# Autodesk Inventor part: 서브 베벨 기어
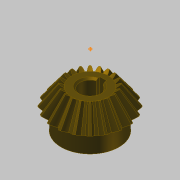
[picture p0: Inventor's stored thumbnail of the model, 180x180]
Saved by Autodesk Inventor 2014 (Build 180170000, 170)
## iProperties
Created: 2016-04
Part Number: 서브 베벨 기어
Material: 강철, 탄소
Document SubType Name: Modeling
Designer: mdu
Categories: <?xml version="1.0" encoding="UTF-16"?> <MemberInstance><Categories><FamilyTemplate><FamilyTemplateParameter ValueType="xs:double" Id="1" ObjectReferenceKey="da
Mass: 135.037 g
Surface Area: 63.6518 cm^2
Volume: 17.1585 cm^3
Density: 7.87 g/cm^3
Appearance: Brindle
CustomPartVersion: 1
Author: mdu
Revision Number: 1
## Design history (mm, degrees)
node "맨 위 점"
node "메쉬 평면2"
sketch "톱니 본체 스케치"
  geometry: L1 (0, 0)-(18.003, -31.331); L2 (18.003, -31.331)-(21.664, -28.891); L3 (21.664, -28.891)-(0, 0); L4 (20, -30)-(0, 0); L5 (10.813, -18.818)-(13.012, -17.352); L6 (18.003, -31.331)-(10.813, -18.818); L7 (21.664, -28.891)-(13.012, -17.352); L8 (0, -39.387)-(0, 6.564) reference; L9 (0, -30)-(21.664, -30)
  constraints: 16 end point, 4 point on line, 3 perpendicular, 2 collinear, 1 horizontal alignment, 1 vertical alignment
  dimensions: "d0" = 40 diameter of L4.start L8 (= da_de); "d1" = 36.00616 diameter of L1.end L8 (= da_dfe); "d2" = 43.3282 diameter of L2.end L8 (= da_dae); "d3" = 14.4 distance between parallel lines of L2 L5 (= da_b); "d4" = 28.8906 vertical distance of L2.end L1.start (= da_ve)
revolve "톱니 본체" sketch "톱니 본체 스케치" stored, may be unused: angle "d5" = 90 deg
node "시작점"
node "톱니 평면"
sketch "시작 스케치"
  geometry: L1 (0, -23.505)-(0, 10.645) reference; L2 (-0.834, -2.928)-(0.834, -2.928); A1 r 8.898 centre (-9.698, -3.713) between (-0.834, -2.928) and (-3.903, 3.04); A2 r 8.898 centre (9.698, -3.713) between (3.903, 3.04) and (0.834, -2.928); A3 r 27.357 centre (0, -24.037) between (3.903, 3.04) and (-3.903, 3.04); 1 further point
  constraints: 6 point on circle, 3 centre point, 3 symmetric about line, 2 end point, 1 coincident, 1 perpendicular, 1 other
  dimensions: "d7" = 8.89846 radius of A1 (= fd_rr); "d8" = 9.69794 horizontal distance of point (0, -24.037) A1.centre (= fd_x); "d9" = 20.32439 vertical distance of point (0, -24.037) A1.centre (= fd_y); "d57" = 27.35701 radius of A3 (= 0.5 x fd_dva + 0.3 x da_he); "d58" = 21.10901 distance from line of A3.centre L2 (= 0.5 x fd_dva - 1.12 x da_he)
node "끝점"
  node "끝 평면"
sketch "3D 스케치 오른쪽"
  node "Helical Curve Right" dims "d65" = 229.90621 (computed from da_dm, da_delta, da_beta), "d66" = 31.5, "d67" = 40 (= da_de), "d68" = -5.88003 (= -da_delta), "d69" = 12.16458 (computed from fd_loft, da_delta)
node "끝 평면 오른쪽"
sketch "끝 스케치 오른쪽"
  geometry: L1 (0, -22.649)-(0, 12.15) reference; L2 (-0.497, -1.72)-(0.497, -1.72); A1 r 5.299 centre (-5.775, -2.187) between (-0.497, -1.72) and (-2.324, 1.834); A2 r 5.299 centre (5.775, -2.187) between (2.324, 1.834) and (0.497, -1.72); A3 r 16.291 centre (0, -14.29) between (2.324, 1.834) and (-2.324, 1.834); 1 further point
  constraints: 6 point on circle, 3 centre point, 3 symmetric about line, 2 end point, 1 coincident, 1 perpendicular, 1 other
  dimensions: "d70" = 5.77526 horizontal distance of A3.centre A1.centre (computed from fd_x, fd_ratio); "d71" = 12.10346 vertical distance of point (0, -14.29) A1.centre (computed from fd_y, fd_ratio); "d72" = 5.29916 radius of A1 (computed from fd_rr, fd_ratio); "d73" = 12.57071 distance from line of point (0, -14.29) L2 (computed from d58, fd_ratio); "d74" = 16.29149 radius of A3 (computed from d57, fd_ratio)
feature "로프트 오른쪽" sketch "끝 스케치 오른쪽" dims "d75" = 0, "d77" = 0, "d79" = 0, "d80" = 90 deg, "d85" = 20, "d92" = 90 deg, "d93" = 90 deg, "da_teethtype" = 0 [user parameter]
sketch "3D 스케치 왼쪽"
  node "Helical Curve Left" dims "d26" = 229.90621 (computed from da_dm, da_delta, da_beta), "d27" = 12.16458 (computed from fd_loft, da_delta), "d28" = 40 (= da_de), "d29" = -5.88003 (= -da_delta)
node "끝 평면 왼쪽"
sketch "끝 스케치 왼쪽" dims "d56" = 10.82768 (derived)
  geometry: L1 (0, -35.087)-(0, 18.089) reference; L2 (-0.497, -1.716)-(0.497, -1.716); A1 r 5.299 centre (-5.775, -2.183) between (-0.497, -1.716) and (-2.324, 1.838); A2 r 5.299 centre (5.775, -2.183) between (2.324, 1.838) and (0.497, -1.716); A3 r 16.291 centre (0, -14.287) between (2.324, 1.838) and (-2.324, 1.838); 2 further points; 1 other entity
  constraints: 6 point on circle, 3 centre point, 3 symmetric about line, 2 end point, 1 coincident, 2 other
  dimensions: "d30" = 5.29916 radius of A1 (computed from fd_rr, fd_ratio); "d31" = 5.77526 horizontal distance of point (0, -14.287) A1.centre (computed from fd_x, fd_ratio); "d32" = 12.10346 vertical distance of A1.centre point (0, -14.287) (computed from fd_y, fd_ratio); "d61" = 16.29149 radius of A3 (computed from d57, fd_ratio); "d62" = 12.57071 distance from line of point (0, -14.287) L2 (computed from d58, fd_ratio)
feature "로프트 왼쪽" sketch "끝 스케치 왼쪽" dims "d35" = 0, "d37" = 0, "d39" = 0, "d40" = 90 deg, "d84" = 10, "d90" = 90 deg, "d91" = 90 deg, "da_teethtype" = 0 [user parameter]
sketch "본체 스케치"
  geometry: L1 (0, -35.038)-(0, -19.531) reference; L2 (18.003, -31.331)-(10.813, -18.818) reference; L3 (10.813, -18.818)-(0, -18.818); L4 (18.003, -31.331)-(0, -31.331)
  constraints: 4 end point, 2 perpendicular, 2 point on line
revolve "본체 고정" sketch "본체 스케치" stored, may be unused: angle "d46" = 90 deg
feature "피치 지름" dims angle "d47" = 90 deg
sketch "스케치8"
  geometry: C1 r 17 at (0, 0); 1 further point
  constraints: 1 centre point, 1 coincident
  dimensions: "d94" = 34 diameter of C1
extrude "돌출1" join sketch "스케치8" distance "d95" = 10; taper "d96" = 0 deg
sketch "스케치9"
  geometry: 1 further point
hole "구멍1" sketch "스케치9" at (0, 0) diameter "d97" = 12; stored, may be unused: countersink angle "d101" = 90 deg, drill point angle "d103" = 118 deg; dims "d98" = 6, "d99" = 4, "d100" = 2, "d102" = 8
sketch "스케치10"
  geometry: 1 further point
sketch "스케치11"
  geometry: 1 further point
sketch "스케치12"
  geometry: L1 (-2, 5.657)-(-2, 7.8); L2 (-2, 7.8)-(2, 7.8); L3 (2, 7.8)-(2, 5.657); A1 r 6 centre (0, 0) between (-2, 5.657) and (2, 5.657) reference; 1 further point
  constraints: 6 end point, 2 parallel, 2 point on circle, 1 perpendicular, 1 vertical
  dimensions: "d104" = 4 distance of L1.end L2.end; "d105" = 13.8 dimension on A1 L2
extrude "돌출2" cut sketch "스케치12" stored distance "d106" = 7; taper "d107" = 0 deg
chamfer "모따기1" distance "d108" = 1; stored, may be unused: second distance "d109" = 2, angle "d110" = 45 deg
body "Solid1"
feature "로프트" dims "d17" = 0, "d18" = 90 deg, "d19" = 0, "d20" = 90 deg, "d89" = 0, "da_teethtype" = 0 [user parameter]
pattern_circular "원형 패턴" dims angle "d22" = 360 deg, "d88" = 0, "da_teethtype" = 0 [user parameter]
pattern_circular "원형 패턴 오른쪽" dims angle "d82" = 360 deg, "da_teethtype" = 0 [user parameter]
pattern_circular "원형 패턴 왼쪽" dims angle "d42" = 360 deg, "da_teethtype" = 0 [user parameter]
sketch "끝 스케치"
  geometry: L1 (0, -15.359)-(0, 6.983) reference; L2 (-0.497, -1.72)-(0.497, -1.72); A1 r 5.299 centre (-5.775, -2.187) between (-0.497, -1.72) and (-2.324, 1.834); A2 r 5.299 centre (5.775, -2.187) between (2.324, 1.834) and (0.497, -1.72); A3 r 16.291 centre (0, -14.29) between (2.324, 1.834) and (-2.324, 1.834); 1 further point
  constraints: 6 point on circle, 3 centre point, 3 symmetric about line, 2 end point, 1 coincident, 1 other
  dimensions: "d12" = 5.29916 radius of A1 (computed from fd_rr, fd_ratio); "d15" = 5.77526 horizontal distance of A1.centre point (0, -14.29) (computed from fd_x, fd_ratio); "d16" = 12.10346 vertical distance of A1.centre point (0, -14.29) (computed from fd_y, fd_ratio); "d59" = 16.29149 radius of A3 (computed from d57, fd_ratio); "d60" = 12.57071 distance from line of A3.centre L2 (computed from d58, fd_ratio)
sketch "Sketch6"
  geometry: L1 (20, -30)-(0, 0) reference; L2 (0, -37.8)-(0, 6.3) reference
body "Srf1"
other parameters: "da_b" = 14.4 [user parameter; used in 2 equation terms], "da_de" = 40 [user parameter; used in 4 equation terms], "da_dae" = 43.3282 [user parameter; used in 2 equation terms], "da_dfe" = 36.00616 [user parameter; used in 1 equation term], "da_le" = 36.05551 [user parameter; used in 1 equation term], "da_omega" = 90 deg [user parameter; used in 1 equation term], "da_beta" = 0 [user parameter; used in 2 equation terms], "da_delta" = 5.88003 [user parameter; used in 8 equation terms], "da_alpha" = 20 deg [user parameter; used in 2 equation terms], "da_he" = 4.4 [user parameter; used in 4 equation terms], "da_ve" = 28.8906 [user parameter; used in 1 equation term], "fd_dv" = 48.07402 (computed from da_de, da_delta) [user parameter; used in 1 equation term], "fd_dva" = 52.07402 (computed from da_dae, da_delta) [user parameter; used in 3 equation terms], "fd_dvb" = 45.1748 (computed from fd_dv, da_alpha) [user parameter; used in 2 equation terms], "da_zv" = 240.37008 [user parameter; used in 1 equation term], "fd_loft" = 14.62 (= da_b + 0.05 x da_he) [user parameter; used in 4 equation terms], "fd_ratio" = 5.95514 (computed from da_le, fd_loft) [user parameter; used in 15 equation terms], "fd_rr" = 8.89846 (computed from fd_dd, fd_dvb) [user parameter; used in 6 equation terms], "fd_angle" = 0.66075 (computed from da_zv) [user parameter; used in 4 equation terms], "fd_x1" = 1.58709 (computed from da_dvw, fd_angle) [user parameter; used in 1 equation term], "fd_y1" = 23.98456 (computed from da_dvw, fd_angle) [user parameter; used in 1 equation term], "fd_x2" = 8.11084 (computed from fd_rr, fd_angle2, fd_angle) [user parameter; used in 1 equation term], "fd_y2" = 3.66016 (computed from fd_rr, fd_angle2, fd_angle) [user parameter; used in 1 equation term], "fd_x" = 9.69794 (= fd_x1 + fd_x2) [user parameter; used in 4 equation terms], "fd_y" = 20.32439 (= fd_y1 - fd_y2) [user parameter; used in 4 equation terms], "fd_angle2" = 3.57832 (computed from fd_dvb, fd_dd, da_alpha) [user parameter; used in 2 equation terms], "fd_dd" = 48.55402 (= fd_dva - 0.8 x da_he) [user parameter; used in 2 equation terms], "da_dvw" = 48.07402 [user parameter; used in 2 equation terms], "d11" = 14.62 (= fd_loft), "da_dm" = 32.01232 [user parameter; used in 2 equation terms], "da_x" = 0 [user parameter], "da_m" = 2 [user parameter], "d48" = 0, "d49" = 0, "d50" = 90 deg (= da_omega), "d51" = 9 deg (computed from da_z), "d52" = 0, "d53" = 0, "d54" = 0
